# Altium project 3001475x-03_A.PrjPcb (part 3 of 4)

## Sheet 10 - CAN, I2C, XBee.SchDoc: CAN, I2C, XBee
size A3; PageSetup: Record=PageOptions¦CenterHorizontal=True¦CenterVertical=True¦PrintScale=0.70¦XCorrection=1.00¦YCorrection=1.00¦PrintKind=0¦BorderSize=5000000¦LeftOffset=0¦BottomOffset=0¦Orientation=2¦PaperLength=4200¦PaperWidth=2970¦Scale=100¦PaperSource=7¦PrintQuality=600¦MediaType=1¦DitherType=10¦PaperKind=A4¦PrintScaleMode=1; Author: Daniel Alesanco; SheetNumber: 10; SheetTotal: 13
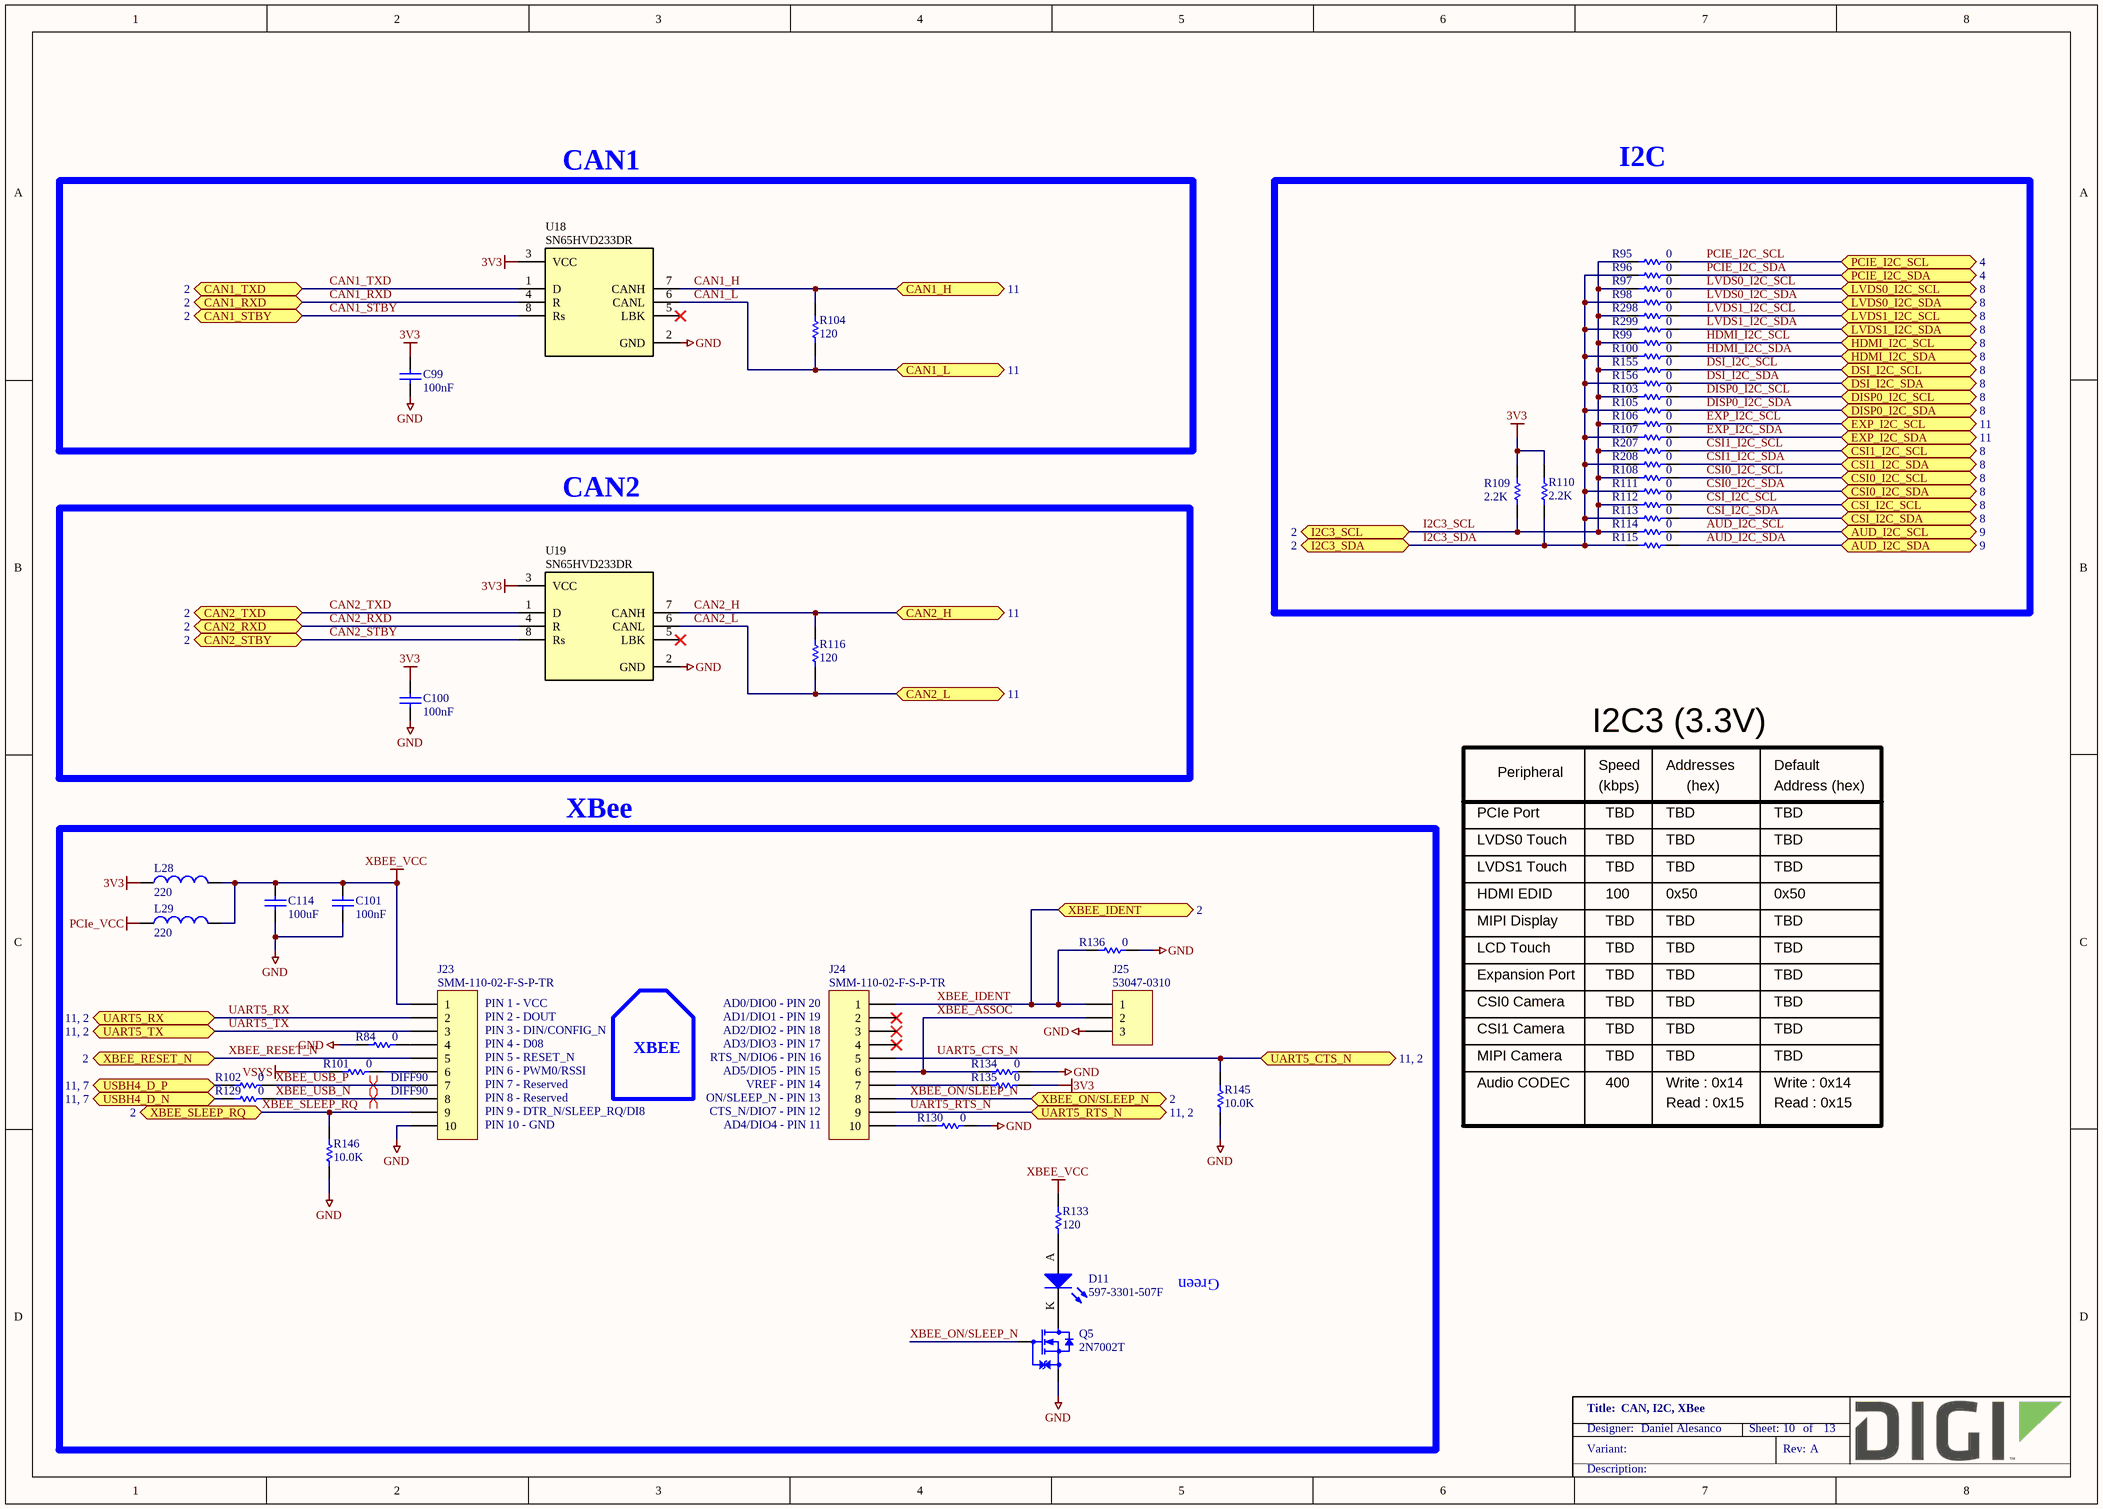
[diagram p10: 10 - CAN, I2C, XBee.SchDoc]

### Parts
C99  100nF  [CAPC1005X55N]
C100  100nF  [CAPC1005X55N]
C101  100nF  [CAPC1005X55N]
C114  100uF  [CAPC3216X190N]
D11  597-3301-507F  [LEDM3020X130N]
J23  SMM-110-02-F-S-P-TR  [Samtec_SMM-110-02-F-S]
J24  SMM-110-02-F-S-P-TR  [Samtec_SMM-110-02-F-S]
J25  Manufacturer_Part_Number: 53047-0310  [MOLEX_53047-0310]  (hidden comment: 1x3P)
L28  220  [INDC2013X110N]
L29  220  [INDC2013X110N]
Q5  2N7002T  [SOTFL50P160X80_GSD-3N]
R84  0  [RESC1005X40N]
R95  0  [RESC1005X40N]
R96  0  [RESC1005X40N]
R97  0  [RESC1005X40N]
R98  0  [RESC1005X40N]
R99  0  [RESC1005X40N]
R100  0  [RESC1005X40N]
R101  0  [RESC1005X40N]
R102  0  [RESC1005X40N]
R103  0  [RESC1005X40N]
R104  120  [RESC1005X40N]
R105  0  [RESC1005X40N]
R106  0  [RESC1005X40N]
R107  0  [RESC1005X40N]
R108  0  [RESC1005X40N]
R109  2.2K  [RESC1005X40N]
R110  2.2K  [RESC1005X40N]
R111  0  [RESC1005X40N]
R112  0  [RESC1005X40N]
R113  0  [RESC1005X40N]
R114  0  [RESC1005X40N]
R115  0  [RESC1005X40N]
R116  120  [RESC1005X40N]
R129  0  [RESC1005X40N]
R130  0  [RESC1005X40N]
R133  120  [RESC1005X40N]
R134  0  [RESC1005X40N]
R135  0  [RESC1005X40N]
R136  0  [RESC1005X40N]
R145  10.0K  [RESC1005X40N]
R146  10.0K  [RESC1005X40N]
R155  0  [RESC1005X40N]
R156  0  [RESC1005X40N]
R207  0  [RESC1005X40N]
R208  0  [RESC1005X40N]
R298  0  [RESC1005X40N]
R299  0  [RESC1005X40N]
U18  SN65HVD233DR  [SOIC127P600X175-8N]
U19  SN65HVD233DR  [SOIC127P600X175-8N]

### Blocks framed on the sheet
CAN1: C99 R104 U18
I2C: R95-R100 R103 R105-R115 R155 R156 R207 R208 R298 R299
CAN2: C100 R116 U19
XBee: C101 C114 D11 J23-J25 L28 L29 Q5 R84 R101 R102 R129 R130 R133-R136 R145 R146

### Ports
AUD_I2C_SCL (bidir, see 9), AUD_I2C_SDA (bidir, see 9), CAN1_H (bidir, see 11), CAN1_L (bidir, see 11), CAN1_RXD (bidir, see 2), CAN1_STBY (bidir, see 2), CAN1_TXD (bidir, see 2), CAN2_H (bidir, see 11), CAN2_L (bidir, see 11), CAN2_RXD (bidir, see 2), CAN2_STBY (bidir, see 2), CAN2_TXD (bidir, see 2), CSI0_I2C_SCL (bidir, see 8), CSI0_I2C_SDA (bidir, see 8), CSI1_I2C_SCL (bidir, see 8), CSI1_I2C_SDA (bidir, see 8), CSI_I2C_SCL (bidir, see 8), CSI_I2C_SDA (bidir, see 8), DISP0_I2C_SCL (bidir, see 8), DISP0_I2C_SDA (bidir, see 8), DSI_I2C_SCL (bidir, see 8), DSI_I2C_SDA (bidir, see 8), EXP_I2C_SCL (bidir, see 11), EXP_I2C_SDA (bidir, see 11), HDMI_I2C_SCL (bidir, see 8), HDMI_I2C_SDA (bidir, see 8), I2C3_SCL (bidir, see 2), I2C3_SDA (bidir, see 2), LVDS0_I2C_SCL (bidir, see 8), LVDS0_I2C_SDA (bidir, see 8), LVDS1_I2C_SCL (bidir, see 8), LVDS1_I2C_SDA (bidir, see 8), PCIE_I2C_SCL (bidir, see 4), PCIE_I2C_SDA (bidir, see 4), UART5_CTS_N (bidir, see 11, 2), UART5_RTS_N (bidir, see 11, 2), UART5_RX (bidir, see 11, 2), UART5_TX (bidir, see 11, 2), USBH4_D_N (bidir, see 11, 7), USBH4_D_P (bidir, see 11, 7), XBEE_IDENT (bidir, see 2), XBEE_ON/SLEEP_N (bidir, see 2), XBEE_RESET_N (bidir, see 2), XBEE_SLEEP_RQ (bidir, see 2)

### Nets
3V3: C99.2 C100.2 L28.1 R109.2 R110.2 R135.2 U18.3(VCC) U19.3(VCC)
GND: C99.1 C100.1 C101.1 C114.1 J23.10 J25.3 Q5.S R84.1 R130.2 R134.2 R136.2 R145.1 R146.1 U18.2(GND) U19.2(GND)
PCIe_VCC: L29.1
VSYS: R101.1
XBEE_VCC: C101.2 C114.2 J23.1 L28.2 L29.2 R133.1
AUD_I2C_SCL: R114.2 ; port AUD_I2C_SCL
AUD_I2C_SDA: R115.2 ; port AUD_I2C_SDA
CAN1_H: R104.2 U18.7(CANH) ; port CAN1_H
CAN1_L: R104.1 U18.6(CANL) ; port CAN1_L
CAN1_RXD: U18.4(R) ; port CAN1_RXD
CAN1_STBY: U18.8(Rs) ; port CAN1_STBY
CAN1_TXD: U18.1(D) ; port CAN1_TXD
CAN2_H: R116.2 U19.7(CANH) ; port CAN2_H
CAN2_L: R116.1 U19.6(CANL) ; port CAN2_L
CAN2_RXD: U19.4(R) ; port CAN2_RXD
CAN2_STBY: U19.8(Rs) ; port CAN2_STBY
CAN2_TXD: U19.1(D) ; port CAN2_TXD
CSI0_I2C_SCL: R108.2 ; port CSI0_I2C_SCL
CSI0_I2C_SDA: R111.2 ; port CSI0_I2C_SDA
CSI1_I2C_SCL: R207.2 ; port CSI1_I2C_SCL
CSI1_I2C_SDA: R208.2 ; port CSI1_I2C_SDA
CSI_I2C_SCL: R112.2 ; port CSI_I2C_SCL
CSI_I2C_SDA: R113.2 ; port CSI_I2C_SDA
DISP0_I2C_SCL: R103.2 ; port DISP0_I2C_SCL
DISP0_I2C_SDA: R105.2 ; port DISP0_I2C_SDA
DSI_I2C_SCL: R155.2 ; port DSI_I2C_SCL
DSI_I2C_SDA: R156.2 ; port DSI_I2C_SDA
EXP_I2C_SCL: R106.2 ; port EXP_I2C_SCL
EXP_I2C_SDA: R107.2 ; port EXP_I2C_SDA
HDMI_I2C_SCL: R99.2 ; port HDMI_I2C_SCL
HDMI_I2C_SDA: R100.2 ; port HDMI_I2C_SDA
I2C3_SCL: R95.1 R97.1 R99.1 R103.1 R106.1 R108.1 R109.1 R112.1 R114.1 R155.1 R207.1 R298.1 ; port I2C3_SCL
I2C3_SDA: R96.1 R98.1 R100.1 R105.1 R107.1 R110.1 R111.1 R113.1 R115.1 R156.1 R208.1 R299.1 ; port I2C3_SDA
LVDS0_I2C_SCL: R97.2 ; port LVDS0_I2C_SCL
LVDS0_I2C_SDA: R98.2 ; port LVDS0_I2C_SDA
LVDS1_I2C_SCL: R298.2 ; port LVDS1_I2C_SCL
LVDS1_I2C_SDA: R299.2 ; port LVDS1_I2C_SDA
PCIE_I2C_SCL: R95.2 ; port PCIE_I2C_SCL
PCIE_I2C_SDA: R96.2 ; port PCIE_I2C_SDA
UART5_CTS_N: J24.5 R145.2 ; port UART5_CTS_N
UART5_RTS_N: J24.9 ; port UART5_RTS_N
UART5_RX: J23.2 ; port UART5_RX
UART5_TX: J23.3 ; port UART5_TX
USBH4_D_N: R129.1 ; port USBH4_D_N
USBH4_D_P: R102.1 ; port USBH4_D_P
XBEE_ASSOC: J24.6 J25.2 R134.1
XBEE_IDENT: J24.1 J25.1 R136.1 ; port XBEE_IDENT
XBEE_ON/SLEEP_N: J24.8 Q5.G ; port XBEE_ON/SLEEP_N
XBEE_RESET_N: J23.5 ; port XBEE_RESET_N
XBEE_SLEEP_RQ: J23.9 R146.2 ; port XBEE_SLEEP_RQ
XBEE_USB_N: J23.8 R129.2
XBEE_USB_P: J23.7 R102.2
NetD11_A: D11.A R133.2
NetD11_K: D11.K Q5.D
NetJ23_4: J23.4 R84.2
NetJ23_6: J23.6 R101.2
NetJ24_7: J24.7 R135.1
NetJ24_10: J24.10 R130.1

Not connected (* = marked no-connect by the designer): J24 2* 3* 4*; U18 5(LBK)*; U19 5(LBK)*

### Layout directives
differential pair; net class DIFF90: XBEE_USB_N, XBEE_USB_P

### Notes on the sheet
- Peripheral
- I2C3 (3.3V)
- Speed
- Addresses
- Default
- PCIe Port
- LVDS0 Touch
- (kbps)
- TBD
- (hex)
- Address (hex)
- HDMI EDID
- LVDS1 Touch
- 100
- 0x50
- MIPI Display
- LCD Touch
- Expansion Port
- (near J23) PIN 1 - VCC
- (near J23) PIN 2 - DOUT
- (near J23) PIN 3 - DIN/CONFIG_N
- (near J23) PIN 4 - D08
- XBEE
- (near J24) AD0/DIO0 - PIN 20
- (near J24) AD1/DIO1 - PIN 19
- (near J24) AD2/DIO2 - PIN 18
- (near J24) AD3/DIO3 - PIN 17
- CSI0 Camera
- CSI1 Camera
- (near J23) PIN 5 - RESET_N
- (near J23) PIN 6 - PWM0/RSSI
- (near J23) PIN 7 - Reserved
- (near J23) PIN 8 - Reserved
- (near J23) PIN 9 - DTR_N/SLEEP_RQ/DI8
- (near J23) PIN 10 - GND
- (near J24) RTS_N/DIO6 - PIN 16
- (near J24) AD5/DIO5 - PIN 15
- (near J24) VREF - PIN 14
- (near J24) ON/SLEEP_N - PIN 13
- (near J24) CTS_N/DIO7 - PIN 12
- (near J24) AD4/DIO4 - PIN 11
- MIPI Camera
- Audio CODEC
- 400
- Write : 0x14
- Read : 0x15
- Green

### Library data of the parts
C99-C101 = 1000006: CAP 100nF 16V 10% X7R 0402; Part_Type: Capacitor; Manufacturer: Murata; Manufacturer_Part_Number: GRM155R71C104KA88D; Component_Life_Cycle_State: CAD Reviewed; Area: 0.95; Project: KITT; Tolerance: 10; Digi_PN: 14050552
C114 = 1000566: CAP CER 100UF 10V 20% X5R 1206; Part_Type: Capacitor; Manufacturer: TDK Corporation; Manufacturer_Part_Number: C3216X5R1A107M; Digi_PN: 14050666; Component_Life_Cycle_State: Reviewed; Area: 7.47; Project: GSM Cell PCB
D11 = 1001189: LED GREEN 573NM 1208 SMD; Manufacturer: Dialight; Digi_PN: 17050183; Component_Life_Cycle_State: Reviewed; Area: 6; Project: CCWMX6_SBC board; Note: 17050846 = Digi PN for GE WDNU II
J23 J24 = 1001495: CONN RCPT 2MM 10POS SMD; Part_Type: Connector; Manufacturer: Samtec; Digi_PN: 19050036; Component_Life_Cycle_State: Reviewed; Area: 105; Project: CCWMX6_SBC board
J25 = 1001183: CONN HEADER 3POS 1.25MM VERT TIN; Part_Type: Connector; Manufacturer: Molex; Digi_PN: 18050349; Component_Life_Cycle_State: Reviewed; Area: 17.6; Project: CCWMX6_SBC board
L28 L29 = 1001174: FERRITE BEAD 220 OHM 2.0A 0805; Manufacturer: Wurth Electronics Inc; Manufacturer_Part_Number: 742792022; Digi_PN: 21000146; Component_Life_Cycle_State: Reviewed; Area: 4.24; Project: CCWMX6_SBC board
Q5 = 1000715: MOSFET N-CH 60V 115MA SOT-523F; Part_Type: Transistor; Manufacturer: Fairchild Semiconductor; Digi_PN: 17050797; Component_Life_Cycle_State: CAD Reviewed; Area: 3.06; Project: SmartMeter2; Note: 17050841 = Digi No. for GE WDNU
R84 R95-R103 R105-R108 R111-R115 R129 R130 R134-R136 R155 R156 R207 R208 R298 R299 = 1000076: RES 0.0 OHM 1/10W 0402 SMD; Part_Type: Resistor; Manufacturer: Panasonic - ECG; Manufacturer_Part_Number: ERJ-2GE0R00X; Component_Life_Cycle_State: Proven; Area: 0.95; Project: Adjustable Foundation; Power_WV_SRF: 10; Digi_PN: 13050387
R104 R116 R133 = 1001158: RES 120 OHM 1/16W 1% 0402 SMD; Part_Type: Resistor; Manufacturer: Yageo; Manufacturer_Part_Number: RC0402FR-07120RL; Digi_PN: 13050832; Component_Life_Cycle_State: Reviewed; Area: 0.95; Project: CCWMX6_SBC board; Note: 13051102 = Digi No. for GE WDNU
R109 R110 = 1001156: RES 2.20K OHM 1/16W 1% 0402 SMD; Part_Type: Resistor; Manufacturer: Yageo; Manufacturer_Part_Number: RC0402FR-072K2L; Digi_PN: 13050699; Component_Life_Cycle_State: Reviewed; Area: 0.95; Project: CCWMX6_SBC board; Note: 13051099 = Digi No. for GE WDNU
R145 R146 = 1000537: RES 10.0K OHM 1/10W 1% 0402 SMD; Part_Type: Resistor; Manufacturer: Panasonic - ECG; Manufacturer_Part_Number: ERJ-2RKF1002X; Component_Life_Cycle_State: CAD Reviewed; Area: 0.95; Project: KITT; Power_WV_SRF: 100; Digi_PN: 13051084
U18 U19 = 1001129: IC CAN TRANSCEIVER 3.3V 8-SOIC; Manufacturer: Texas Instruments; Digi_PN: TA02540; Component_Life_Cycle_State: Reviewed; Area: 20; Project: CCWMX6_SBC board

## Sheet 11 - Expansion Connectors, User LEDs.SchDoc: Expansion Connectors, User LEDs
size A3; PageSetup: Record=PageOptions¦CenterHorizontal=True¦CenterVertical=True¦PrintScale=0.70¦XCorrection=1.00¦YCorrection=1.00¦PrintKind=0¦BorderSize=5000000¦LeftOffset=0¦BottomOffset=0¦Orientation=2¦PaperLength=4200¦PaperWidth=2970¦Scale=100¦PaperSource=7¦PrintQuality=600¦MediaType=1¦DitherType=10¦PaperKind=A4¦PrintScaleMode=1; Author: Daniel Alesanco; SheetNumber: 11; SheetTotal: 13
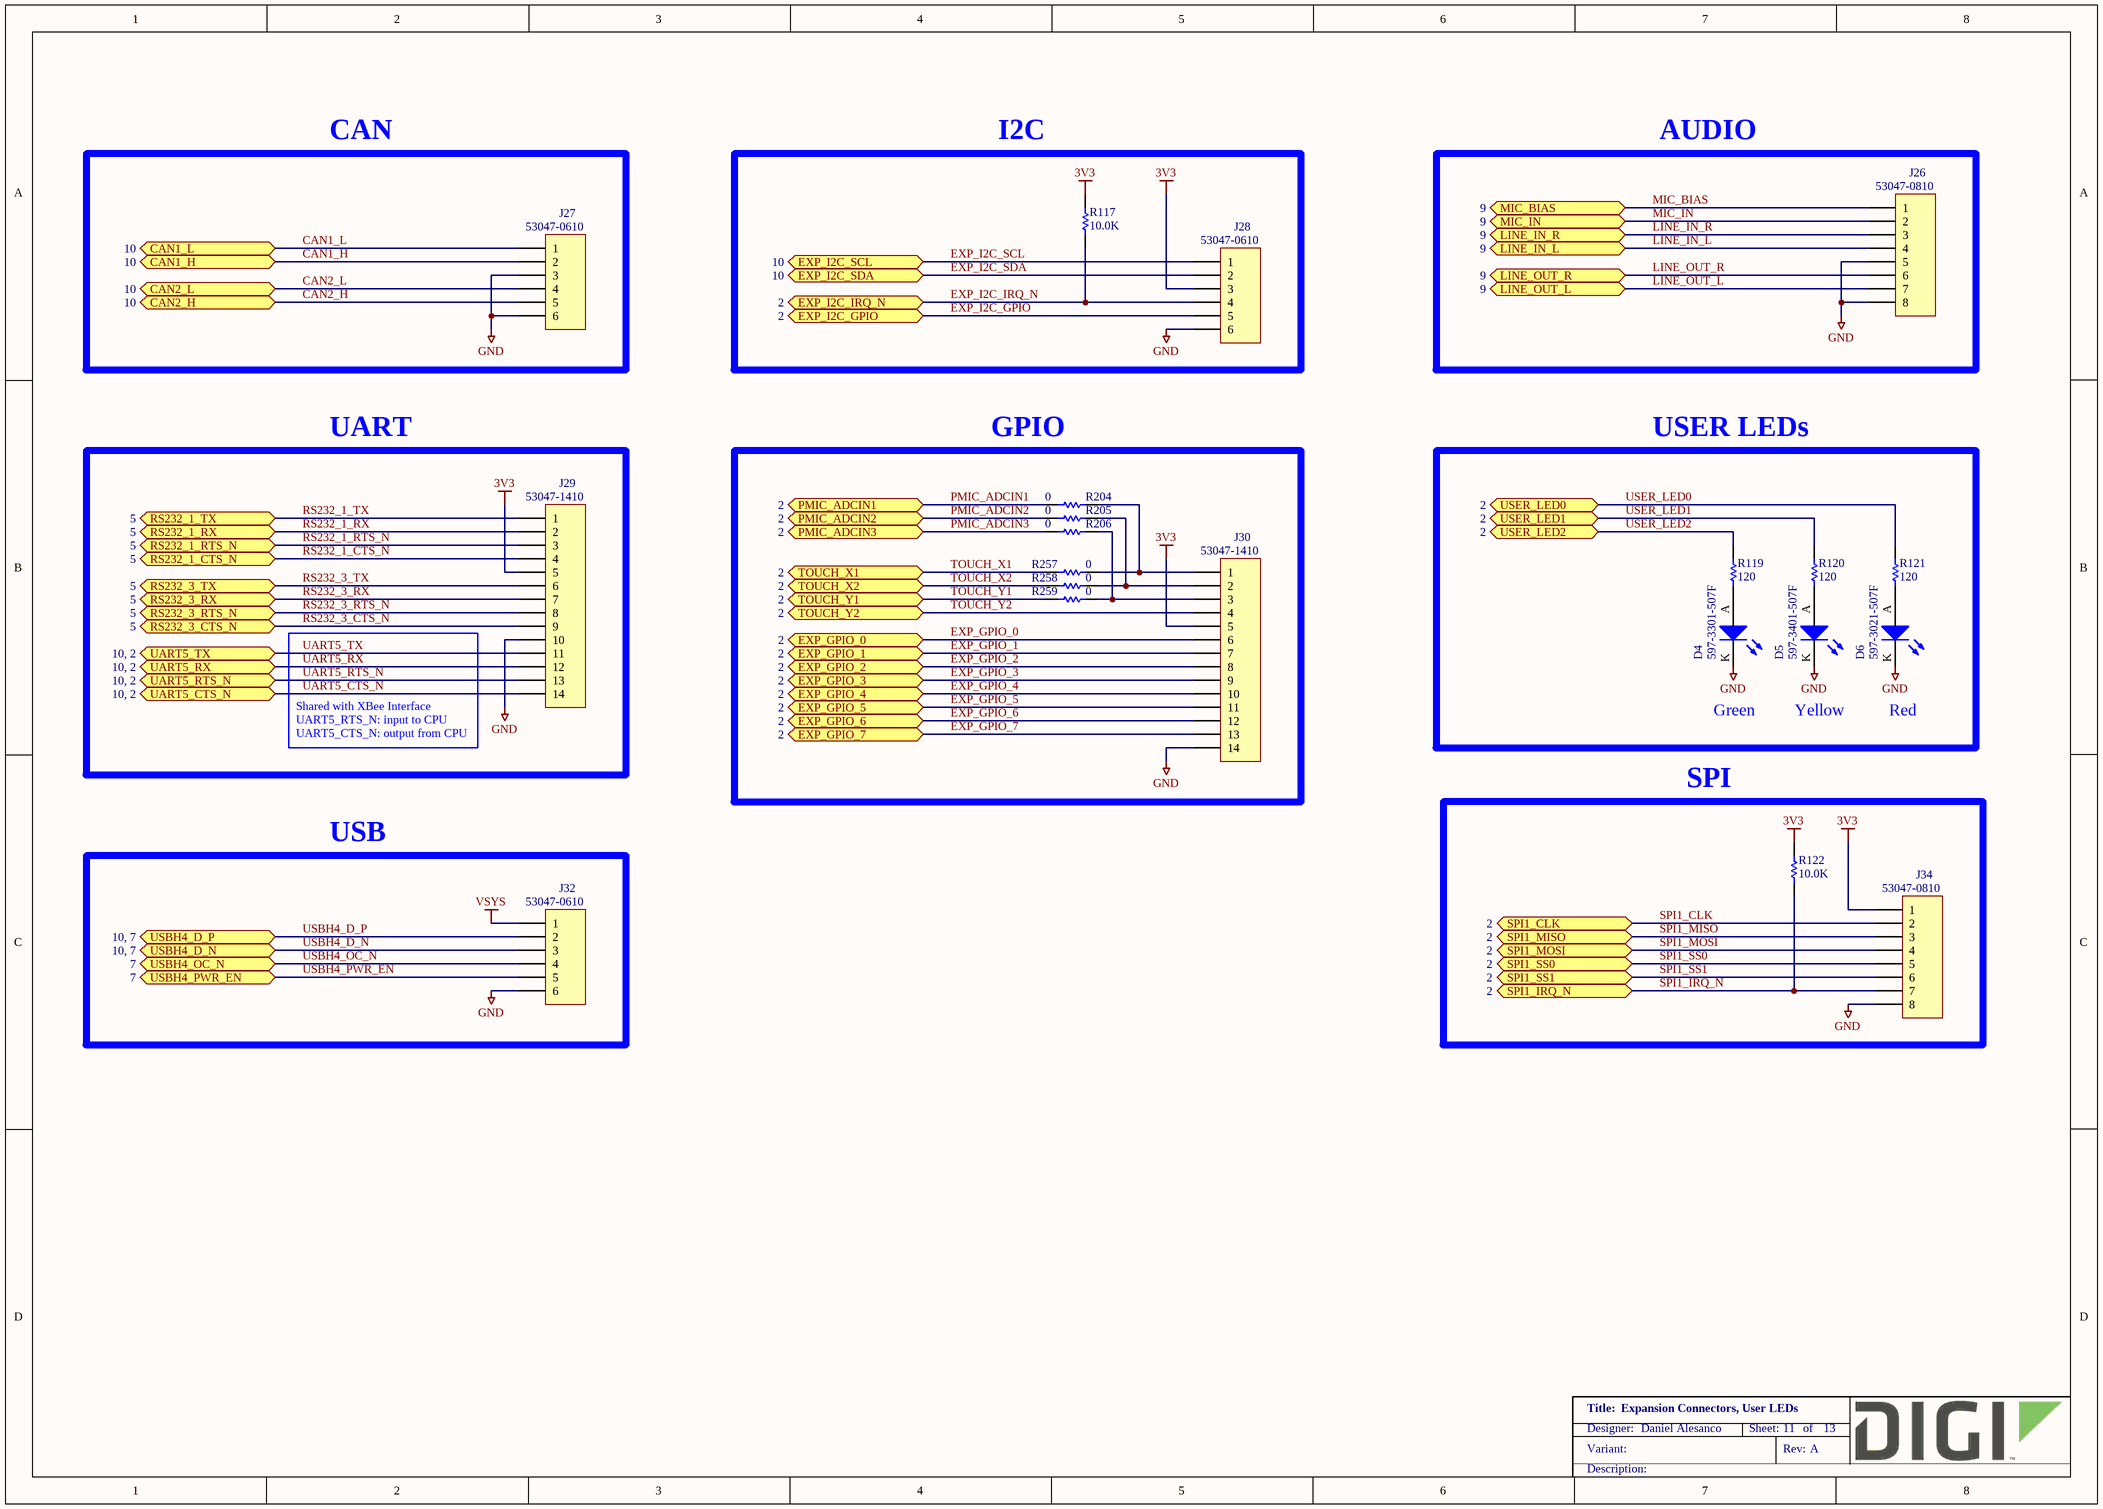
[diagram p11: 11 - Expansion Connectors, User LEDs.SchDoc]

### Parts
D4  597-3301-507F  [LEDM3020X130N]
D5  597-3401-507F  [LEDM3020X130N]
D6  597-3021-507F  [LEDM3020X130N]
J26  Manufacturer_Part_Number: 53047-0810  [MOLEX_53047-0810]  (hidden comment: 1x8P)
J27  Manufacturer_Part_Number: 53047-0610  [MOLEX_53047-0610]  (hidden comment: 1x6P)
J28  Manufacturer_Part_Number: 53047-0610  [MOLEX_53047-0610]  (hidden comment: 1x6P)
J29  Manufacturer_Part_Number: 53047-1410  [MOLEX_53047-1410]  (hidden comment: 1x14P)
J30  Manufacturer_Part_Number: 53047-1410  [MOLEX_53047-1410]  (hidden comment: 1x14P)
J32  Manufacturer_Part_Number: 53047-0610  [MOLEX_53047-0610]  (hidden comment: 1x6P)
J34  Manufacturer_Part_Number: 53047-0810  [MOLEX_53047-0810]  (hidden comment: 1x8P)
R117  10.0K  [RESC1005X40N]
R119  120  [RESC1005X40N]
R120  120  [RESC1005X40N]
R121  120  [RESC1005X40N]
R122  10.0K  [RESC1005X40N]
R204  0  [RESC1005X40N]
R205  0  [RESC1005X40N]
R206  0  [RESC1005X40N]
R257  0  [RESC1005X40N]
R258  0  [RESC1005X40N]
R259  0  [RESC1005X40N]

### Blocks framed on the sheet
CAN: J27
I2C: J28 R117
AUDIO: J26
UART: J29
GPIO: J30 R204-R206 R257-R259
USER LEDs: D4-D6 R119-R121
SPI: J34 R122
USB: J32

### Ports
CAN1_H (bidir, see 10), CAN1_L (bidir, see 10), CAN2_H (bidir, see 10), CAN2_L (bidir, see 10), EXP_GPIO_0 (bidir, see 2), EXP_GPIO_1 (bidir, see 2), EXP_GPIO_2 (bidir, see 2), EXP_GPIO_3 (bidir, see 2), EXP_GPIO_4 (bidir, see 2), EXP_GPIO_5 (bidir, see 2), EXP_GPIO_6 (bidir, see 2), EXP_GPIO_7 (bidir, see 2), EXP_I2C_GPIO (bidir, see 2), EXP_I2C_IRQ_N (bidir, see 2), EXP_I2C_SCL (bidir, see 10), EXP_I2C_SDA (bidir, see 10), LINE_IN_L (bidir, see 9), LINE_IN_R (bidir, see 9), LINE_OUT_L (bidir, see 9), LINE_OUT_R (bidir, see 9), MIC_BIAS (bidir, see 9), MIC_IN (bidir, see 9), PMIC_ADCIN1 (bidir, see 2), PMIC_ADCIN2 (bidir, see 2), PMIC_ADCIN3 (bidir, see 2), RS232_1_CTS_N (bidir, see 5), RS232_1_RTS_N (bidir, see 5), RS232_1_RX (bidir, see 5), RS232_1_TX (bidir, see 5), RS232_3_CTS_N (bidir, see 5), RS232_3_RTS_N (bidir, see 5), RS232_3_RX (bidir, see 5), RS232_3_TX (bidir, see 5), SPI1_CLK (bidir, see 2), SPI1_IRQ_N (bidir, see 2), SPI1_MISO (bidir, see 2), SPI1_MOSI (bidir, see 2), SPI1_SS0 (bidir, see 2), SPI1_SS1 (bidir, see 2), TOUCH_X1 (bidir, see 2), TOUCH_X2 (bidir, see 2), TOUCH_Y1 (bidir, see 2), TOUCH_Y2 (bidir, see 2), UART5_CTS_N (bidir, see 10, 2), UART5_RTS_N (bidir, see 10, 2), UART5_RX (bidir, see 10, 2), UART5_TX (bidir, see 10, 2), USBH4_D_N (bidir, see 10, 7), USBH4_D_P (bidir, see 10, 7), USBH4_OC_N (bidir, see 7), USBH4_PWR_EN (bidir, see 7), USER_LED0 (bidir, see 2), USER_LED1 (bidir, see 2), USER_LED2 (bidir, see 2)

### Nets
3V3: J28.3 J29.5 J30.5 J34.1 R117.1 R122.1
GND: D4.K D5.K D6.K J26.5 J26.8 J27.3 J27.6 J28.6 J29.10 J30.14 J32.6 J34.8
VSYS: J32.1
CAN1_H: J27.2 ; port CAN1_H
CAN1_L: J27.1 ; port CAN1_L
CAN2_H: J27.5 ; port CAN2_H
CAN2_L: J27.4 ; port CAN2_L
EXP_GPIO_0: J30.6 ; port EXP_GPIO_0
EXP_GPIO_1: J30.7 ; port EXP_GPIO_1
EXP_GPIO_2: J30.8 ; port EXP_GPIO_2
EXP_GPIO_3: J30.9 ; port EXP_GPIO_3
EXP_GPIO_4: J30.10 ; port EXP_GPIO_4
EXP_GPIO_5: J30.11 ; port EXP_GPIO_5
EXP_GPIO_6: J30.12 ; port EXP_GPIO_6
EXP_GPIO_7: J30.13 ; port EXP_GPIO_7
EXP_I2C_GPIO: J28.5 ; port EXP_I2C_GPIO
EXP_I2C_IRQ_N: J28.4 R117.2 ; port EXP_I2C_IRQ_N
EXP_I2C_SCL: J28.1 ; port EXP_I2C_SCL
EXP_I2C_SDA: J28.2 ; port EXP_I2C_SDA
LINE_IN_L: J26.4 ; port LINE_IN_L
LINE_IN_R: J26.3 ; port LINE_IN_R
LINE_OUT_L: J26.7 ; port LINE_OUT_L
LINE_OUT_R: J26.6 ; port LINE_OUT_R
MIC_BIAS: J26.1 ; port MIC_BIAS
MIC_IN: J26.2 ; port MIC_IN
PMIC_ADCIN1: R204.1 ; port PMIC_ADCIN1
PMIC_ADCIN2: R205.1 ; port PMIC_ADCIN2
PMIC_ADCIN3: R206.1 ; port PMIC_ADCIN3
RS232_1_CTS_N: J29.4 ; port RS232_1_CTS_N
RS232_1_RTS_N: J29.3 ; port RS232_1_RTS_N
RS232_1_RX: J29.2 ; port RS232_1_RX
RS232_1_TX: J29.1 ; port RS232_1_TX
RS232_3_CTS_N: J29.9 ; port RS232_3_CTS_N
RS232_3_RTS_N: J29.8 ; port RS232_3_RTS_N
RS232_3_RX: J29.7 ; port RS232_3_RX
RS232_3_TX: J29.6 ; port RS232_3_TX
SPI1_CLK: J34.2 ; port SPI1_CLK
SPI1_IRQ_N: J34.7 R122.2 ; port SPI1_IRQ_N
SPI1_MISO: J34.3 ; port SPI1_MISO
SPI1_MOSI: J34.4 ; port SPI1_MOSI
SPI1_SS0: J34.5 ; port SPI1_SS0
SPI1_SS1: J34.6 ; port SPI1_SS1
TOUCH_X1: R257.1 ; port TOUCH_X1
TOUCH_X2: R258.1 ; port TOUCH_X2
TOUCH_Y1: R259.1 ; port TOUCH_Y1
TOUCH_Y2: J30.4 ; port TOUCH_Y2
UART5_CTS_N: J29.14 ; port UART5_CTS_N
UART5_RTS_N: J29.13 ; port UART5_RTS_N
UART5_RX: J29.12 ; port UART5_RX
UART5_TX: J29.11 ; port UART5_TX
USBH4_D_N: J32.3 ; port USBH4_D_N
USBH4_D_P: J32.2 ; port USBH4_D_P
USBH4_OC_N: J32.4 ; port USBH4_OC_N
USBH4_PWR_EN: J32.5 ; port USBH4_PWR_EN
USER_LED0: R121.2 ; port USER_LED0
USER_LED1: R120.2 ; port USER_LED1
USER_LED2: R119.2 ; port USER_LED2
NetD4_A: D4.A R119.1
NetD5_A: D5.A R120.1
NetD6_A: D6.A R121.1
NetJ30_1: J30.1 R204.2 R257.2
NetJ30_2: J30.2 R205.2 R258.2
NetJ30_3: J30.3 R206.2 R259.2

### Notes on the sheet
- Shared with XBee Interface
- UART5_RTS_N: input to CPU
- Green
- Yellow
- Red
- UART5_CTS_N: output from CPU

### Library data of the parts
D4 = 1001189: as D11 on sheet 10 - CAN, I2C, XBee
D5 = 1001188: LED YELLOW 588NM 1208 SMD; Manufacturer: Dialight; Digi_PN: 17050387; Component_Life_Cycle_State: Reviewed; Area: 6; Project: CCWMX6_SBC board; Note: 17050842 = Digi No. for GE WDNU
D6 = 1001190: LED RED 653NM 20MA 1208 SMD; Manufacturer: Dialight; Digi_PN: 17050184; Component_Life_Cycle_State: Reviewed; Area: 6; Project: CCWMX6_SBC board
J26 J34 = 1001139: CONN HEADER 8POS 1.25MM VERT TIN; Part_Type: Connector; Manufacturer: Molex; Digi_PN: 18050346; Component_Life_Cycle_State: Reviewed; Area: 37.6; Project: CCWMX6_SBC board
J27 J28 J32 = 1001138: CONN HEADER 6POS 1.25MM VERT TIN; Part_Type: Connector; Manufacturer: Molex; Digi_PN: 18050345; Component_Life_Cycle_State: Reviewed; Area: 29.6; Project: CCWMX6_SBC board
J29 J30 = 1001140: CONN HEADER 14POS 1.25MM STR TIN; Part_Type: Connector; Manufacturer: Molex; Digi_PN: 18050347; Component_Life_Cycle_State: Reviewed; Area: 61.6; Project: CCWMX6_SBC board
R117 R122 = 1000537: as R145 on sheet 10 - CAN, I2C, XBee
R119-R121 = 1001158: as R104 on sheet 10 - CAN, I2C, XBee
R204-R206 R257-R259 = 1000076: as R84 on sheet 10 - CAN, I2C, XBee

## Sheet 12 - GPIO Table, System Power rails.SchDoc: GPIO Table, System Power Rails
size A3; PageSetup: Record=PageOptions¦CenterHorizontal=True¦CenterVertical=True¦PrintScale=1.01¦XCorrection=1.00¦YCorrection=1.00¦PrintKind=0¦BorderSize=5000000¦LeftOffset=0¦BottomOffset=0¦Orientation=2¦PaperLength=4200¦PaperWidth=2970¦Scale=100¦PaperSource=15¦PrintQuality=600¦MediaType=1¦DitherType=10¦PrintScaleMode=1¦PaperKind=A3¦PaperIndex=8; Author: Daniel Alesanco; SheetNumber: 12; SheetTotal: 13
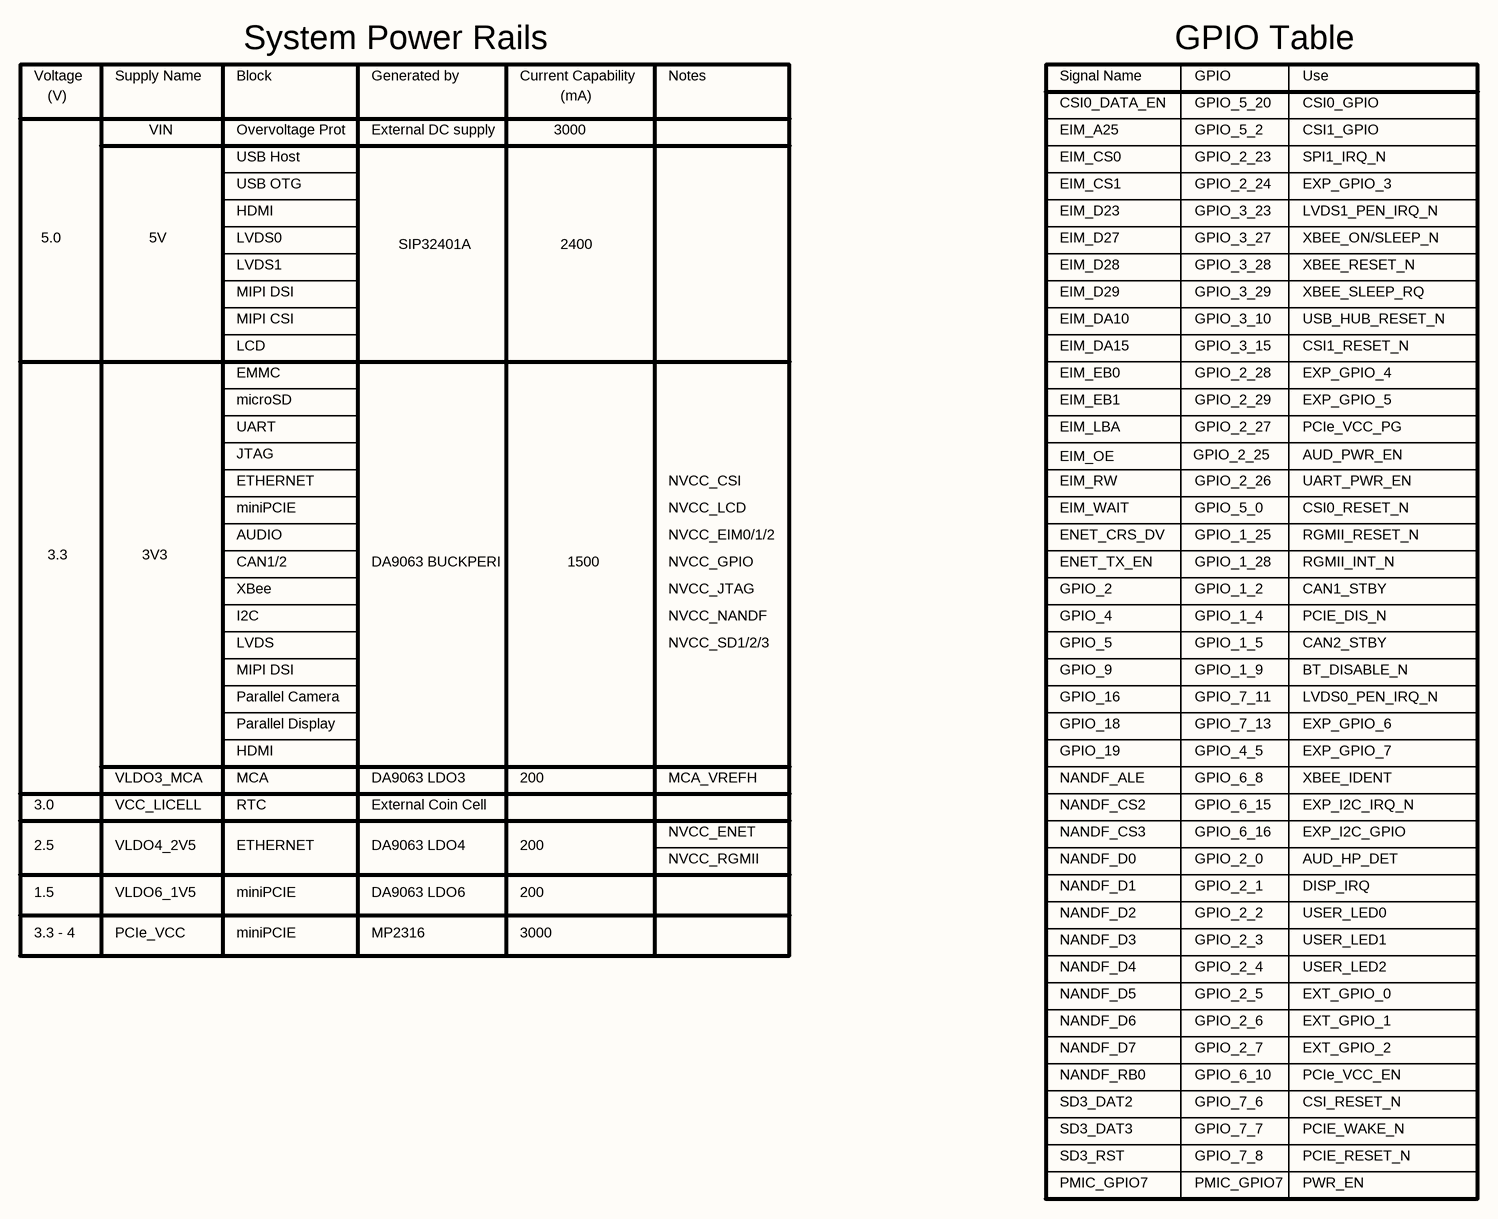
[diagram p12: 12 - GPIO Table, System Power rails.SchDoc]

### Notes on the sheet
- Voltage
- (V)
- Supply Name
- Block
- System Power Rails
- Generated by
- Current Capability
- (mA)
- Notes
- Signal Name
- CSI0_DATA_EN
- GPIO Table
- GPIO
- GPIO_5_20
- Use
- CSI0_GPIO
- VIN
- Overvoltage Prot
- USB Host
- External DC supply
- 3000
- EIM_CS0
- EIM_A25
- GPIO_2_23
- GPIO_5_2
- SPI1_IRQ_N
- CSI1_GPIO
- 5.0
- 5V
- USB OTG
- HDMI
- LVDS0
- SIP32401A
- 2400
- EIM_CS1
- EIM_D23
- EIM_D27
- GPIO_2_24
- GPIO_3_23
- GPIO_3_27
- EXP_GPIO_3
- LVDS1_PEN_IRQ_N
- XBEE_ON/SLEEP_N
- MIPI DSI
- LVDS1
- EIM_D28
- EIM_D29
- GPIO_3_28
- GPIO_3_29
- XBEE_RESET_N
- XBEE_SLEEP_RQ
- MIPI CSI
- LCD
- EMMC
- EIM_DA10
- EIM_DA15
- EIM_EB0
- GPIO_3_10
- GPIO_3_15
- GPIO_2_28
- USB_HUB_RESET_N
- CSI1_RESET_N
- EXP_GPIO_4
- microSD
- UART
- EIM_EB1
- EIM_LBA
- GPIO_2_29
- GPIO_2_27
- EXP_GPIO_5
- PCIe_VCC_PG
- JTAG
- ETHERNET
- miniPCIE
- NVCC_CSI
- NVCC_LCD
- EIM_WAIT
- EIM_OE
- EIM_RW
- GPIO_2_25
- GPIO_5_0
- GPIO_2_26
- CSI0_RESET_N
- AUD_PWR_EN
- UART_PWR_EN
- 3.3
- 3V3
- AUDIO
- CAN1/2
- DA9063 BUCKPERI
- 1500
- NVCC_EIM0/1/2
- NVCC_GPIO
- ENET_CRS_DV
- ENET_TX_EN
- GPIO_1_25
- GPIO_1_28
- RGMII_RESET_N
- RGMII_INT_N
- XBee
- I2C
- LVDS
- NVCC_JTAG
- NVCC_NANDF
- NVCC_SD1/2/3
- GPIO_2
- GPIO_4
- GPIO_5
- GPIO_1_2
- GPIO_1_4
- GPIO_1_5
- CAN1_STBY
- PCIE_DIS_N
- CAN2_STBY
- Parallel Camera
- GPIO_16
- GPIO_9
- GPIO_1_9
- GPIO_7_11
- BT_DISABLE_N
- LVDS0_PEN_IRQ_N
- VLDO3_MCA
- Parallel Display
- MCA
- DA9063 LDO3
- 200
- MCA_VREFH
- GPIO_18
- GPIO_19
- NANDF_ALE
- GPIO_7_13
- GPIO_4_5
- GPIO_6_8
- EXP_GPIO_6
- EXP_GPIO_7
- XBEE_IDENT
- 3.0
- 2.5
- VCC_LICELL
- VLDO4_2V5
- RTC
- External Coin Cell
- DA9063 LDO4
- NVCC_ENET
- NANDF_CS2
- NANDF_CS3
- GPIO_6_15
- GPIO_6_16
- EXP_I2C_IRQ_N
- EXP_I2C_GPIO
- 1.5
- VLDO6_1V5
- DA9063 LDO6
- NVCC_RGMII
- NANDF_D0
- NANDF_D1
- NANDF_D2
- GPIO_2_0
- GPIO_2_1
- GPIO_2_2
- AUD_HP_DET
- DISP_IRQ
- USER_LED0
- 3.3 - 4
- PCIe_VCC
- MP2316
- NANDF_D3
- NANDF_D4
- GPIO_2_3
- GPIO_2_4
- USER_LED1
- USER_LED2
- NANDF_D5
- NANDF_D6
- NANDF_D7
- GPIO_2_5
- GPIO_2_6
- GPIO_2_7
- EXT_GPIO_0
- EXT_GPIO_1
- EXT_GPIO_2
- SD3_DAT2
- NANDF_RB0
- GPIO_7_6
- GPIO_6_10
- CSI_RESET_N
- PCIe_VCC_EN
- SD3_DAT3
- PMIC_GPIO7
- SD3_RST
- GPIO_7_7
- GPIO_7_8
- PCIE_WAKE_N
- PWR_EN
- PCIE_RESET_N

## Sheet 13 - History, Mechanicals.SchDoc: History
size A3; PageSetup: Record=PageOptions¦CenterHorizontal=True¦CenterVertical=True¦PrintScale=1.01¦XCorrection=1.00¦YCorrection=1.00¦PrintKind=0¦BorderSize=5000000¦LeftOffset=0¦BottomOffset=0¦Orientation=2¦PaperLength=4200¦PaperWidth=2970¦Scale=100¦PaperSource=15¦PrintQuality=600¦MediaType=1¦DitherType=10¦PrintScaleMode=1¦PaperKind=A3¦PaperIndex=8; Author: Daniel Alesanco; SheetNumber: 13; SheetTotal: 13
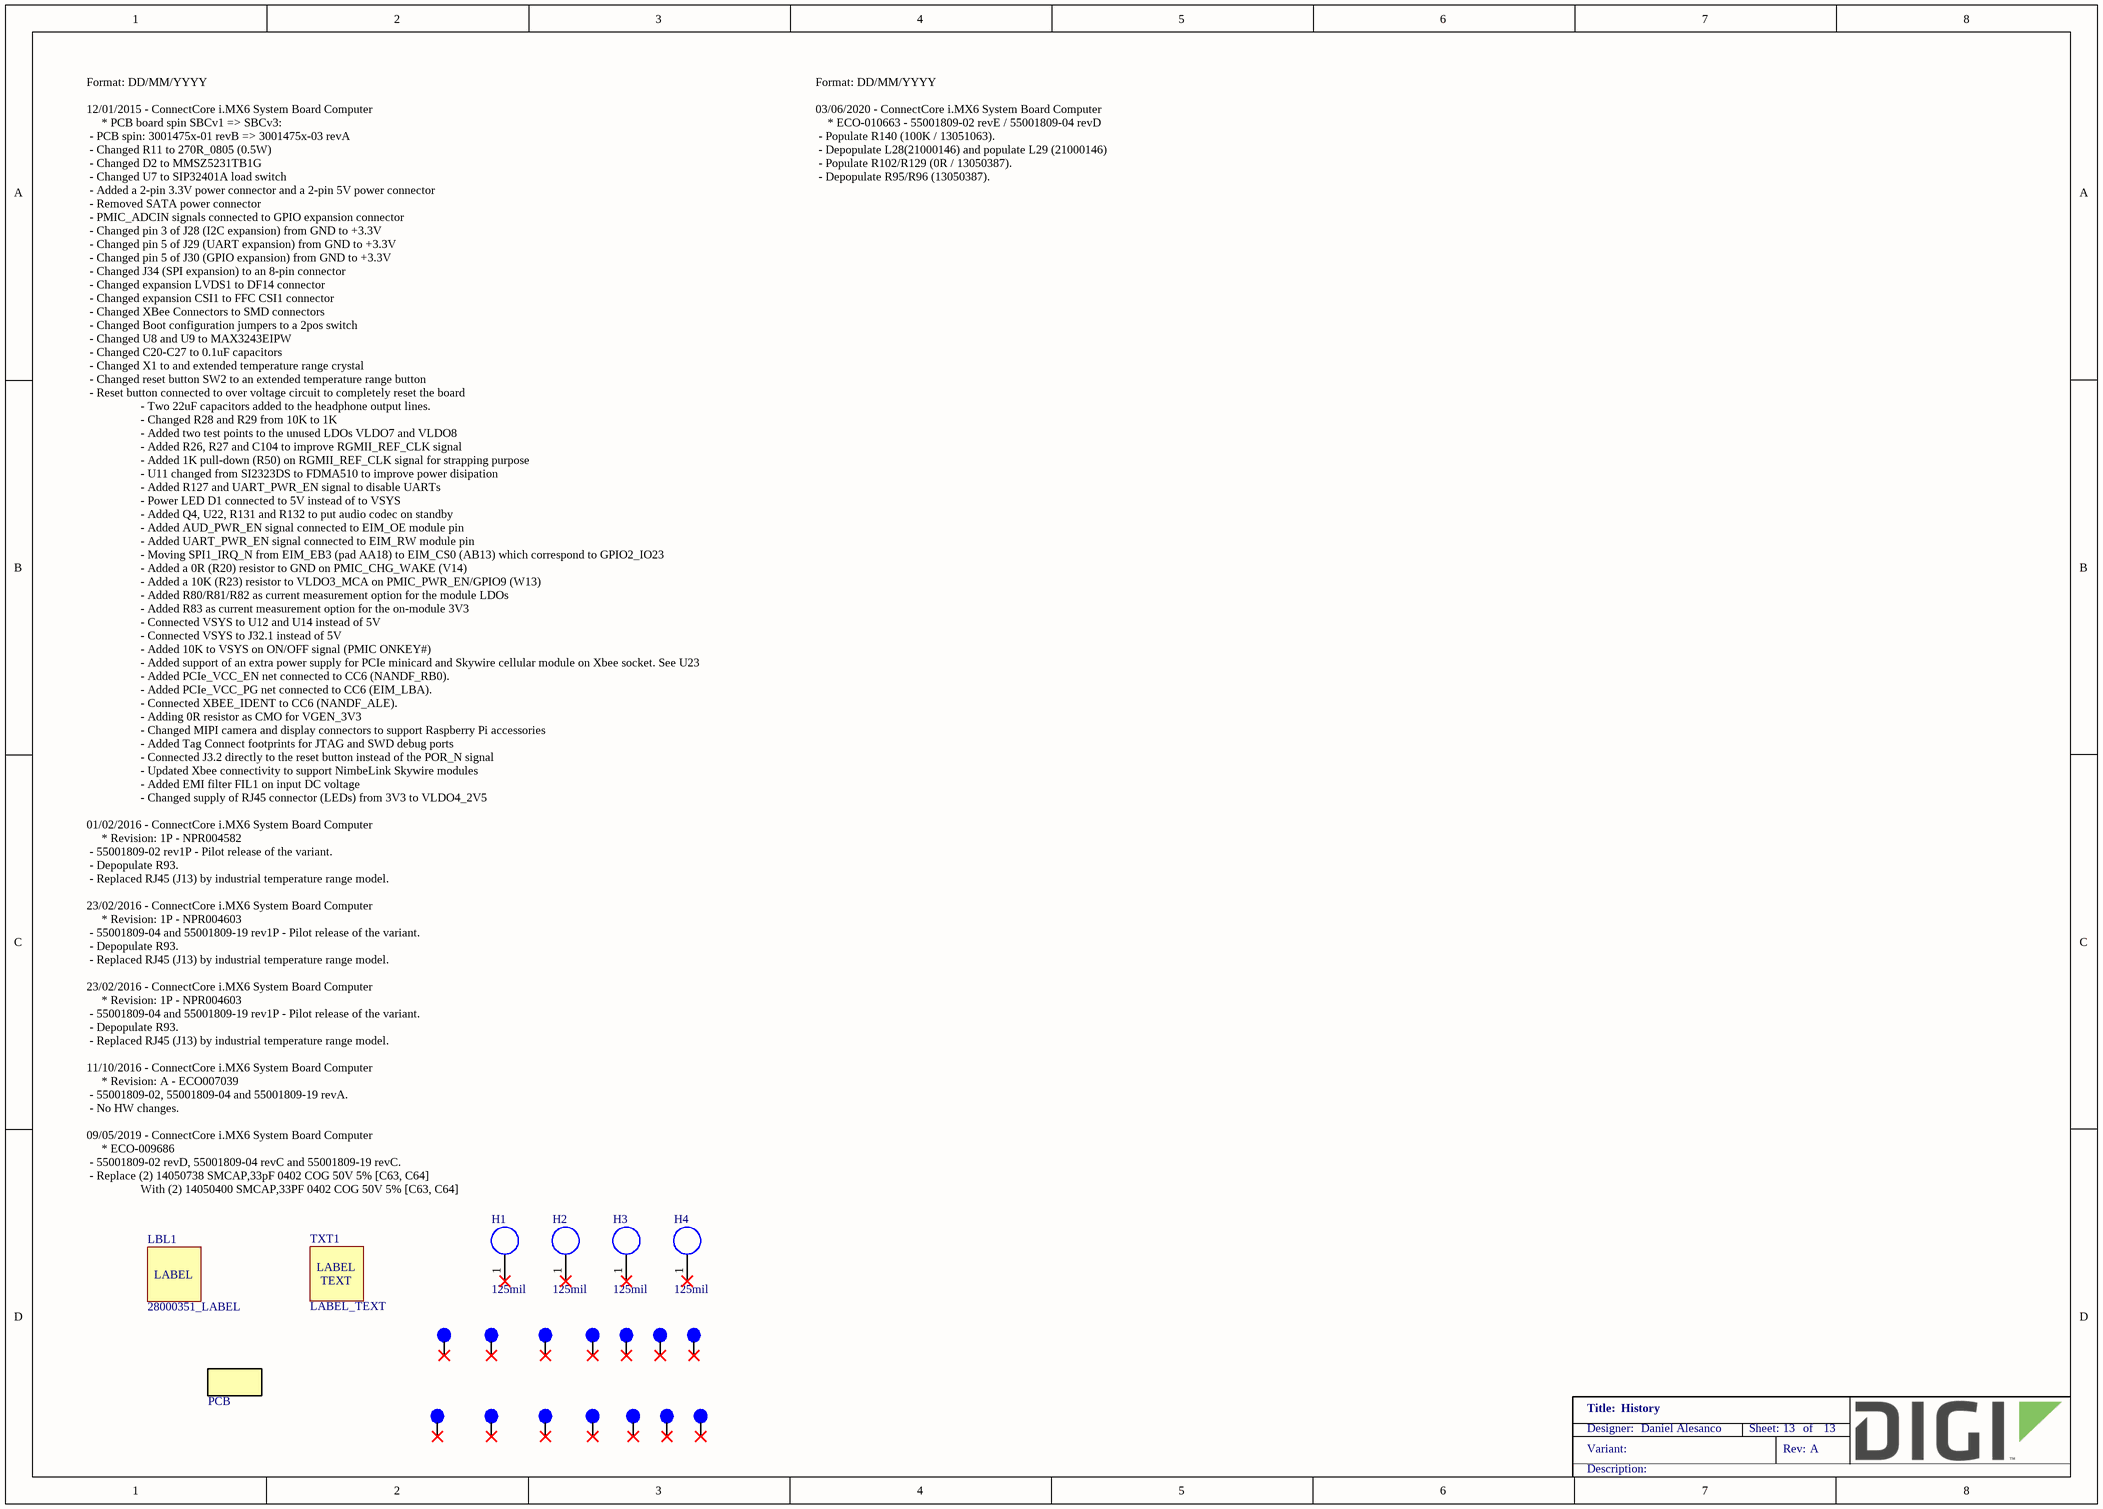
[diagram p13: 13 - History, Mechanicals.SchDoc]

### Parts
FIDUCIAL1  40mil FID  [fiducial_40mil_round]  (value not drawn)  (no BOM)
FIDUCIAL2  40mil FID  [fiducial_40mil_round]  (value not drawn)  (no BOM)
FIDUCIAL3  40mil FID  [fiducial_40mil_round]  (value not drawn)  (no BOM)
FIDUCIAL4  40mil FID  [fiducial_40mil_round]  (value not drawn)  (no BOM)
FIDUCIAL5  40mil FID  [fiducial_40mil_round]  (value not drawn)  (no BOM)
FIDUCIAL6  40mil FID  [fiducial_40mil_round]  (value not drawn)  (no BOM)
FIDUCIAL7  40mil FID  [fiducial_40mil_round]  (value not drawn)  (no BOM)
FIDUCIAL8  40mil FID  [fiducial_40mil_round]  (value not drawn)  (no BOM)
FIDUCIAL9  40mil FID  [fiducial_40mil_round]  (value not drawn)  (no BOM)
FIDUCIAL10  40mil FID  [fiducial_40mil_round]  (value not drawn)  (no BOM)
FIDUCIAL11  40mil FID  [fiducial_40mil_round]  (value not drawn)  (no BOM)
FIDUCIAL12  40mil FID  [fiducial_40mil_round]  (value not drawn)  (no BOM)
FIDUCIAL13  40mil FID  [fiducial_40mil_round]  (value not drawn)  (no BOM)
FIDUCIAL14  40mil FID  [fiducial_40mil_round]  (value not drawn)  (no BOM)
H1  125mil  [MH_185_125_NP]
H2  125mil  [MH_185_125_NP]
H3  125mil  [MH_185_125_NP]
H4  125mil  [MH_185_125_NP]
LBL1  28000351_LABEL  [LABEL_10x10]
PCB1  PCB  [PCBNUMBER]
TXT1  LABEL_TEXT  [0201-2.3]

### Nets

Not connected (* = marked no-connect by the designer): FIDUCIAL1 1(Fid_1)*; FIDUCIAL2 1(Fid_1)*; FIDUCIAL3 1(Fid_1)*; FIDUCIAL4 1(Fid_1)*; FIDUCIAL5 1(Fid_1)*; FIDUCIAL6 1(Fid_1)*; FIDUCIAL7 1(Fid_1)*; FIDUCIAL8 1(Fid_1)*; FIDUCIAL9 1(Fid_1)*; FIDUCIAL10 1(Fid_1)*; FIDUCIAL11 1(Fid_1)*; FIDUCIAL12 1(Fid_1)*; FIDUCIAL13 1(Fid_1)*; FIDUCIAL14 1(Fid_1)*; H1 1(TOOL)*; H2 1(TOOL)*; H3 1(TOOL)*; H4 1(TOOL)*

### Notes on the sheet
- Format: DD/MM/YYYY
  12/01/2015 - ConnectCore i.MX6 System Board Computer
  * PCB board spin SBCv1 => SBCv3:
  - PCB spin: 3001475x-01 revB => 3001475x-03 revA
  - Changed R11 to 270R_0805 (0.5W)
  - Changed D2 to MMSZ5231TB1G
  - Changed U7 to SIP32401A load switch
  - Added a 2-pin 3.3V power connector and a 2-pin 5V power connector
  - Removed SATA power connector
  - PMIC_ADCIN signals connected to GPIO expansion connector
  - Changed pin 3 of J28 (I2C expansion) from GND to +3.3V
  - Changed pin 5 of J29 (UART expansion) from GND to +3.3V
  - Changed pin 5 of J30 (GPIO expansion) from GND to +3.3V
  - Changed J34 (SPI expansion) to an 8-pin connector
  - Changed expansion LVDS1 to DF14 connector
  - Changed expansion CSI1 to FFC CSI1 connector
  - Changed XBee Connectors to SMD connectors
  - Changed Boot configuration jumpers to a 2pos switch
  - Changed U8 and U9 to MAX3243EIPW
  - Changed C20-C27 to 0.1uF capacitors
  - Changed X1 to and extended temperature range crystal
  - Changed reset button SW2 to an extended temperature range button
  - Reset button connected to over voltage circuit to completely reset the board
  - Two 22uF capacitors added to the headphone output lines.
  - Changed R28 and R29 from 10K to 1K
  - Added two test points to the unused LDOs VLDO7 and VLDO8
  - Added R26, R27 and C104 to improve RGMII_REF_CLK signal
  - Added 1K pull-down (R50) on RGMII_REF_CLK signal for strapping purpose
  - U11 changed from SI2323DS to FDMA510 to improve power disipation
  - Added R127 and UART_PWR_EN signal to disable UARTs
  - Power LED D1 connected to 5V instead of to VSYS
  - Added Q4, U22, R131 and R132 to put audio codec on standby
  - Added AUD_PWR_EN signal connected to EIM_OE module pin
  - Added UART_PWR_EN signal connected to EIM_RW module pin
  - Moving SPI1_IRQ_N from EIM_EB3 (pad AA18) to EIM_CS0 (AB13) which correspond to GPIO2_IO23
  - Added a 0R (R20) resistor to GND on PMIC_CHG_WAKE (V14)
  - Added a 10K (R23) resistor to VLDO3_MCA on PMIC_PWR_EN/GPIO9 (W13)
  - Added R80/R81/R82 as current measurement option for the module LDOs
  - Added R83 as current measurement option for the on-module 3V3
  - Connected VSYS to U12 and U14 instead of 5V
  - Connected VSYS to J32.1 instead of 5V
  - Added 10K to VSYS on ON/OFF signal (PMIC ONKEY#)
  - Added support of an extra power supply for PCIe minicard and Skywire cellular module on Xbee socket. See U23
  - Added PCIe_VCC_EN net connected to CC6 (NANDF_RB0).
  - Added PCIe_VCC_PG net connected to CC6 (EIM_LBA).
  - Connected XBEE_IDENT to CC6 (NANDF_ALE).
  - Adding 0R resistor as CMO for VGEN_3V3
  - Changed MIPI camera and display connectors to support Raspberry Pi accessories
  - Added Tag Connect footprints for JTAG and SWD debug ports
  - Connected J3.2 directly to the reset button instead of the POR_N signal
  - Updated Xbee connectivity to support NimbeLink Skywire modules
  - Added EMI filter FIL1 on input DC voltage
  - Changed supply of RJ45 connector (LEDs) from 3V3 to VLDO4_2V5
  01/02/2016 - ConnectCore i.MX6 System Board Computer
  * Revision: 1P - NPR004582
  - 55001809-02 rev1P - Pilot release of the variant.
  - Depopulate R93.
  - Replaced RJ45 (J13) by industrial temperature range model.
  23/02/2016 - ConnectCore i.MX6 System Board Computer
  * Revision: 1P - NPR004603
  - 55001809-04 and 55001809-19 rev1P - Pilot release of the variant.
  - Depopulate R93.
  - Replaced RJ45 (J13) by industrial temperature range model.
  23/02/2016 - ConnectCore i.MX6 System Board Computer
  * Revision: 1P - NPR004603
  - 55001809-04 and 55001809-19 rev1P - Pilot release of the variant.
  - Depopulate R93.
  - Replaced RJ45 (J13) by industrial temperature range model.
  11/10/2016 - ConnectCore i.MX6 System Board Computer
  * Revision: A - ECO007039
  - 55001809-02, 55001809-04 and 55001809-19 revA.
  - No HW changes.
  09/05/2019 - ConnectCore i.MX6 System Board Computer
  * ECO-009686
  - 55001809-02 revD, 55001809-04 revC and 55001809-19 revC.
  - Replace (2) 14050738 SMCAP,33pF 0402 COG 50V 5% [C63, C64]
  With (2) 14050400 SMCAP,33PF 0402 COG 50V 5% [C63, C64]
- Format: DD/MM/YYYY
  03/06/2020 - ConnectCore i.MX6 System Board Computer
  * ECO-010663 - 55001809-02 revE / 55001809-04 revD
  - Populate R140 (100K / 13051063).
  - Depopulate L28(21000146) and populate L29 (21000146)
  - Populate R102/R129 (0R / 13050387).
  - Depopulate R95/R96 (13050387).

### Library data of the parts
FIDUCIAL1-FIDUCIAL14 = CAD0023: 40 Mil Round Fiducial; Part_Type: Mechanical; Component_Life_Cycle_State: Reviewed; Area: 1; Project: SDR Prototype RF Board
H1-H4 = CAD0006: NPTH for Tooling, 0.125in dia.; Part_Type: Mechanical; Component_Life_Cycle_State: Proven; Area: 0.98; Project: Adjustable Foundation
LBL1 = 1002170: LBL,Poly White Blank 0.40x0.40; Manufacturer: 3M; Manufacturer_Part_Number: TAAE-014000; Noplace: False; Component_Life_Cycle_State: Created; Area: 100; Project: CCWMX6_SBC board
PCB1 = 3000137: PCB CCWM6_SBC_v0.3; Digi_PN: 30014752-02; Component_Life_Cycle_State: Created; Project: CCWMX6_SBC board
TXT1 = LABEL_TEXT: Text,0.39 x 0.39 2D PN SN 55M LBL; Noplace: False; Digi_PN: 95017001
